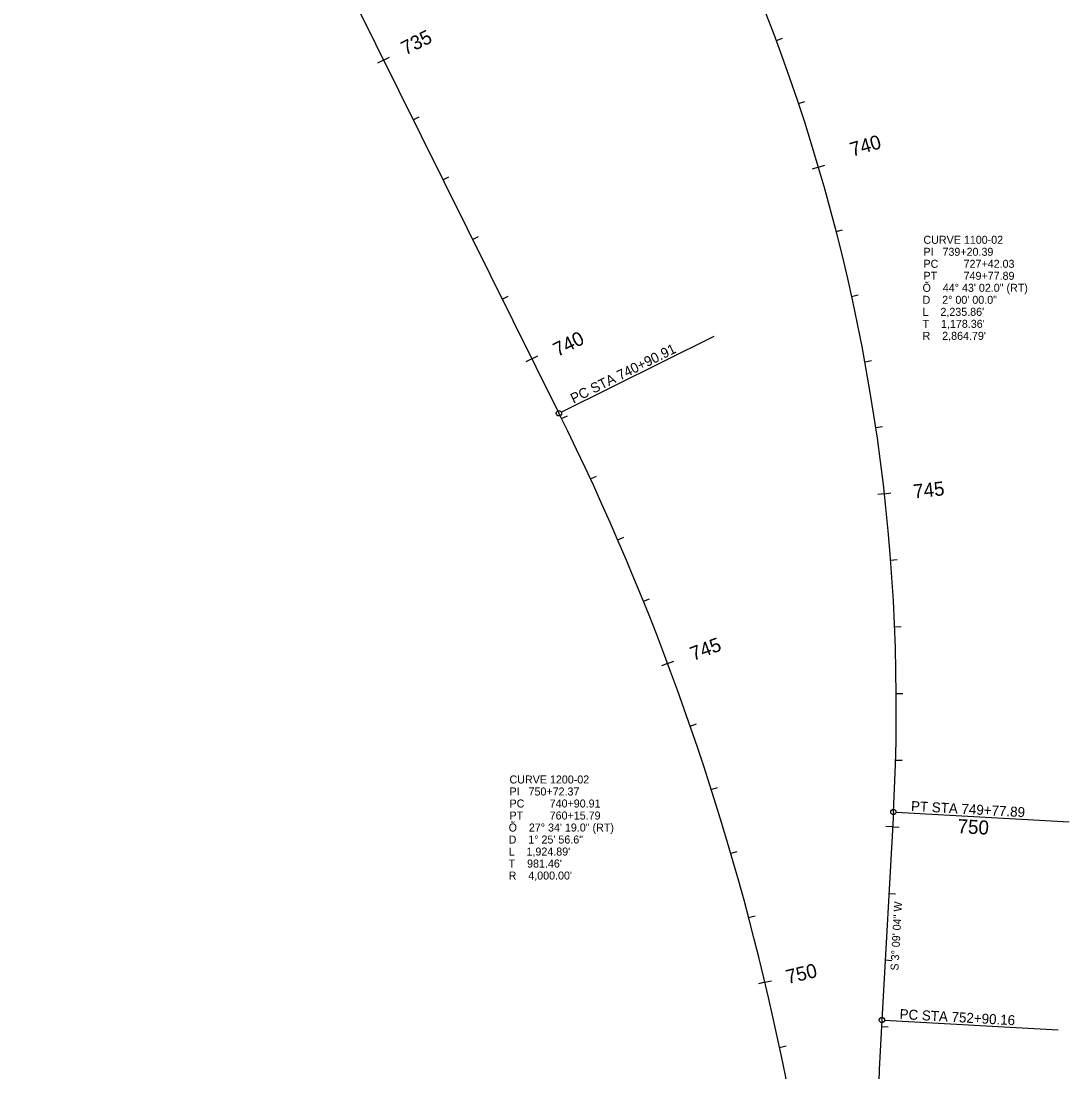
# Model space of a CAD drawing. Extents: x 2819977 to 2827606, y 113942 to 150283.
# Drawn here: x 2822516 to 2824087, y 143732 to 145308 of the extents above; entities that cross this region are included whole.
import ezdxf

# ---------------------------------------------------------------- set-up
doc = ezdxf.new("R2010")
doc.units = 0
for name, color, linetype in [('Level 63', 7, 'Continuous'), ('Roadway-Safety', 7, 'Continuous'), ('Roadway-Signs', 7, 'Continuous'), ('Roadway-Walls', 7, 'Continuous'), ('Utility-Power', 7, 'Continuous')]:
    doc.layers.add(name, color=color, linetype=linetype)

msp = doc.modelspace()

# ---------------------------------------------------------------- linework, layer by layer
at = {"layer": 'Level 63'}
for centre in [(2823824, 144121.8), (2823806.8, 143810)]:
    msp.add_circle(centre, 4, dxfattribs=at)
at = {"layer": 'Roadway-Safety'}
for p, q in [((2823326, 144721.4), (2823555.2, 144835.3)), ((2823828, 144121.6), (2824087.4, 144107.3)), ((2823810.8, 143809.8), (2824070.9, 143795.5))]:
    msp.add_line(p, q, dxfattribs=at)
at = {"layer": 'Utility-Power'}
for p, q in [((2822515.7, 146343.3), (2823322.4, 144719.6)), ((2823648.6, 145278.2), (2823657.9, 145281.7)), ((2823059.5, 145248.8), (2823050.5, 145244.4)), ((2823059.5, 145248.8), (2823068.4, 145253.2)), ((2823681.8, 145183.9), (2823691.3, 145187)), ((2823103.9, 145159.2), (2823112.9, 145163.7)), ((2823711.7, 145088.5), (2823721.3, 145091.3)), ((2823711.7, 145088.5), (2823702.1, 145085.6)), ((2823148.4, 145069.7), (2823157.4, 145074.1)), ((2823192.9, 144980.1), (2823201.9, 144984.6)), ((2823738.3, 144992.1), (2823747.9, 144994.6)), ((2823237.4, 144890.6), (2823246.4, 144895)), ((2823761.4, 144894.8), (2823771.2, 144896.9)), ((2823281.9, 144801), (2823273, 144796.6)), ((2823281.9, 144801), (2823290.9, 144805.5)), ((2823781.2, 144796.8), (2823791.1, 144798.6)), ((2823326.4, 144711.5), (2823335.4, 144715.9)), ((2823797.6, 144698.1), (2823807.5, 144699.6)), ((2823369.6, 144621.3), (2823378.7, 144625.5)), ((2823810.5, 144599), (2823800.5, 144597.9)), ((2823810.5, 144599), (2823820.4, 144600.1)), ((2823410.5, 144530), (2823419.7, 144534)), ((2823819.9, 144499.4), (2823829.8, 144500.2)), ((2823449.1, 144437.8), (2823458.4, 144441.5)), ((2823825.8, 144399.6), (2823835.8, 144400)), ((2823485.4, 144344.6), (2823476, 144341.1)), ((2823485.4, 144344.6), (2823494.7, 144348.1)), ((2823828.3, 144299.6), (2823838.3, 144299.7)), ((2823519.3, 144250.5), (2823528.8, 144253.8)), ((2823827.2, 144199.6), (2823837.2, 144199.4)), ((2823550.9, 144155.7), (2823560.4, 144158.7)), ((2823824, 144121.8), (2823806.8, 143810)), ((2823822.8, 144099.7), (2823812.8, 144100.3)), ((2823822.8, 144099.7), (2823832.8, 144099.2)), ((2823580.1, 144060), (2823589.7, 144062.8)), ((2823817.3, 143999.9), (2823827.3, 143999.3)), ((2823606.9, 143963.7), (2823616.6, 143966.2)), ((2823811.8, 143900.1), (2823821.8, 143899.5)), ((2823631.3, 143866.7), (2823621.6, 143864.4)), ((2823631.3, 143866.7), (2823641, 143869)), ((2823806.3, 143800.2), (2823816.3, 143799.7)), ((2823653.3, 143769.1), (2823663, 143771.2))]:
    msp.add_line(p, q, dxfattribs=at)
msp.add_circle((2823322.4, 144719.6), 4, dxfattribs=at)
for centre, radius, start, end in [((2820963.6, 144279.3), 2864.8, 356.8489, 41.5661), ((2819740.2, 142939.8), 4000, 358.849, 26.4209), ((2840781.1, 142875.6), 17000, 176.84893, 178.84897)]:
    msp.add_arc(centre, radius, start, end, dxfattribs=at)

# ---------------------------------------------------------------- texts
at = {"layer": 'Roadway-Safety'}
for s, rotation, p in [('PC STA 740+90.91', 26.4209, (2823344.3, 144733.9)), ('PT STA 749+77.89', 356.8489, (2823850.1, 144123.4)), ('PC STA 752+90.16', 356.8489, (2823833, 143811.6))]:
    msp.add_text(s, height=15, rotation=rotation, dxfattribs=at).set_placement(p)
at = {"layer": 'Roadway-Signs'}
msp.add_text('S 3%%d 09\' 04" W', height=12, rotation=86.8489, dxfattribs=at).set_placement((2823831.5, 143883.9))
at = {"layer": 'Roadway-Walls'}
for s, p in [('CURVE 1100-02', (2823869.1, 144973.6)), ('PI   739+20.39', (2823869.1, 144955.6)), ('PC', (2823869.1, 144937.6)), ('727+42.03', (2823929.3, 144937.6)), ('Õ    44%%d 43\' 02.0" (RT)', (2823867.8, 144901.6)), ('PT', (2823869.1, 144919.6)), ('749+77.89', (2823929.3, 144919.6)), ('D    2%%d 00\' 00.0"', (2823867.8, 144883.6)), ("L    2,235.86'", (2823867.8, 144865.6)), ("T    1,178.36'", (2823867.8, 144847.6)), ("R    2,864.79'", (2823867.8, 144829.6)), ('CURVE 1200-02', (2823248.3, 144164.6)), ('PI   750+72.37', (2823248.3, 144146.6)), ('PC', (2823248.3, 144128.6)), ('740+90.91', (2823308.5, 144128.6)), ('PT', (2823248.3, 144110.6)), ('760+15.79', (2823308.5, 144110.6)), ('Õ    27%%d 34\' 19.0" (RT)', (2823247, 144092.6)), ('D    1%%d 25\' 56.6"', (2823247, 144074.6)), ("L    1,924.89'", (2823247, 144056.6)), ("T    981.46'", (2823247, 144038.6)), ("R    4,000.00'", (2823247, 144020.6))]:
    msp.add_text(s, height=12, dxfattribs=at).set_placement(p)
at = {"layer": 'Utility-Power'}
for s, rotation, p in [(' 735', 26.4209, (2823085.2, 145252.3)), (' 740', 16.4068, (2823755, 145101.9)), (' 740', 26.4209, (2823313.4, 144800.4)), (' 745', 6.4068, (2823847.2, 144590.8)), (' 745', 20.5611, (2823516.6, 144345.4)), (' 750', 356.8489, (2823912.1, 144090.8)), (' 750', 13.3992, (2823658, 143862.2))]:
    msp.add_text(s, height=21, rotation=rotation, dxfattribs=at).set_placement(p)

doc.saveas('drawing.dxf')
